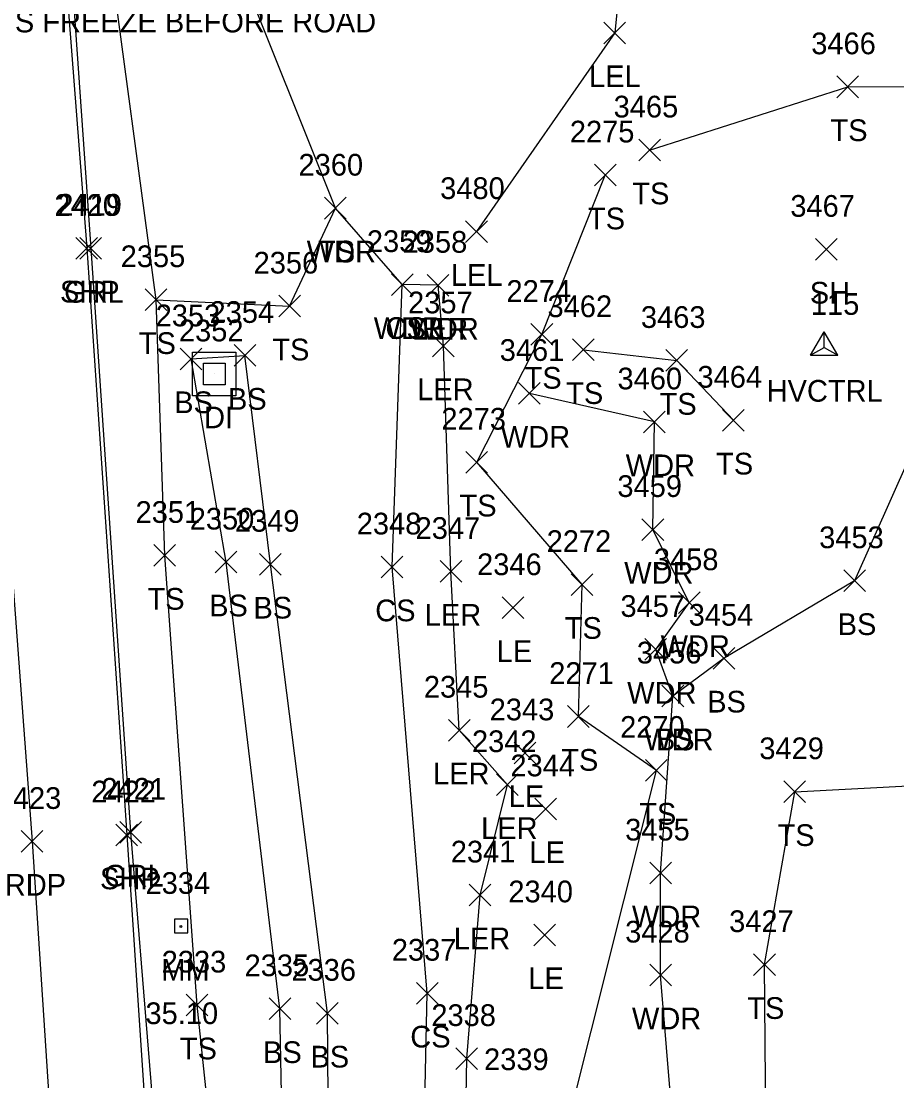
# Model space of a CAD drawing. Extents: x 1650221 to 1650634, y 244606 to 249996.
# Drawn here: x 1650339.8 to 1650420.5, y 246721.6 to 246819.2 of the extents above; entities that cross this region are included whole.
import ezdxf

# ---------------------------------------------------------------- set-up
doc = ezdxf.new("R2010")
doc.units = 0
for name, color, linetype in [('C_A', 7, 'Continuous'), ('C_I', 7, 'Continuous'), ('CPSM', 7, 'Continuous'), ('D_A', 7, 'Continuous'), ('D_I', 7, 'Continuous'), ('DS', 7, 'Continuous'), ('L_A', 7, 'Continuous'), ('L_I', 7, 'Continuous'), ('L_TIC', 7, 'Continuous'), ('LARO', 7, 'Continuous'), ('LAWA', 7, 'Continuous'), ('LELB', 7, 'Continuous'), ('P_A', 7, 'Continuous'), ('P_I', 7, 'Continuous'), ('P_TIC', 7, 'Continuous'), ('PET', 7, 'Continuous'), ('PSP', 7, 'Continuous'), ('R_A', 7, 'Continuous'), ('R_I', 7, 'Continuous'), ('R_TIC', 7, 'Continuous'), ('RGR', 7, 'Continuous'), ('S_A', 7, 'Continuous'), ('S_C', 7, 'Continuous'), ('S_I', 7, 'Continuous'), ('SRM', 7, 'Continuous')]:
    doc.layers.add(name, color=color, linetype=linetype)

msp = doc.modelspace()

# ---------------------------------------------------------------- linework, layer by layer
at = {"layer": 'CPSM'}
for p, q in [((1650412.524, 246788.462), (1650413.774, 246790.627)), ((1650415.024, 246788.462), (1650413.774, 246790.627)), ((1650413.774, 246789.183), (1650413.774, 246790.627)), ((1650412.524, 246788.462), (1650413.774, 246789.183)), ((1650413.774, 246789.183), (1650413.774, 246789.183)), ((1650413.774, 246789.183), (1650415.024, 246788.462)), ((1650412.524, 246788.462), (1650415.024, 246788.462))]:
    msp.add_line(p, q, dxfattribs=at)
at = {"layer": 'DS'}
for p, q in [((1650355.573, 246788.737), (1650359.573, 246788.737)), ((1650355.573, 246784.737), (1650355.573, 246788.737)), ((1650359.573, 246788.737), (1650359.573, 246784.737)), ((1650356.573, 246785.737), (1650356.573, 246787.737)), ((1650356.573, 246787.737), (1650358.573, 246787.737)), ((1650358.573, 246787.737), (1650358.573, 246785.737)), ((1650357.578, 246786.738), (1650357.578, 246786.738)), ((1650357.578, 246786.738), (1650357.578, 246786.738)), ((1650358.573, 246785.737), (1650356.573, 246785.737)), ((1650359.573, 246784.737), (1650355.573, 246784.737))]:
    msp.add_line(p, q, dxfattribs=at)
at = {"layer": 'L_TIC'}
for points in [[(1650393.466, 246817.159), (1650395.466, 246819.159)], [(1650395.466, 246817.159), (1650393.466, 246819.159)], [(1650414.942, 246812.191), (1650416.942, 246814.191)], [(1650416.942, 246812.191), (1650414.942, 246814.191)], [(1650396.679, 246806.368), (1650398.679, 246808.368)], [(1650398.679, 246806.368), (1650396.679, 246808.368)], [(1650392.596, 246804.064), (1650394.596, 246806.064)], [(1650394.596, 246804.064), (1650392.596, 246806.064)], [(1650367.73, 246801.011), (1650369.73, 246803.011)], [(1650369.73, 246801.011), (1650367.73, 246803.011)], [(1650367.73, 246801.011), (1650369.73, 246803.011)], [(1650369.73, 246801.011), (1650367.73, 246803.011)], [(1650380.734, 246798.853), (1650382.734, 246800.853)], [(1650382.734, 246798.853), (1650380.734, 246800.853)], [(1650412.958, 246797.218), (1650414.958, 246799.218)], [(1650414.958, 246797.218), (1650412.958, 246799.218)], [(1650373.901, 246793.969), (1650375.901, 246795.969)], [(1650375.901, 246793.969), (1650373.901, 246795.969)], [(1650373.901, 246793.969), (1650375.901, 246795.969)], [(1650375.901, 246793.969), (1650373.901, 246795.969)], [(1650377.195, 246793.908), (1650379.195, 246795.908)], [(1650379.195, 246793.908), (1650377.195, 246795.908)], [(1650377.195, 246793.908), (1650379.195, 246795.908)], [(1650379.195, 246793.908), (1650377.195, 246795.908)], [(1650351.21, 246792.578), (1650353.21, 246794.578)], [(1650353.21, 246792.578), (1650351.21, 246794.578)], [(1650351.21, 246792.578), (1650353.21, 246794.578)], [(1650353.21, 246792.578), (1650351.21, 246794.578)], [(1650363.513, 246791.988), (1650365.513, 246793.988)], [(1650365.513, 246791.988), (1650363.513, 246793.988)], [(1650386.756, 246789.379), (1650388.756, 246791.379)], [(1650388.756, 246789.379), (1650386.756, 246791.379)], [(1650377.69, 246788.322), (1650379.69, 246790.322)], [(1650379.69, 246788.322), (1650377.69, 246790.322)], [(1650390.587, 246787.973), (1650392.587, 246789.973)], [(1650392.587, 246787.973), (1650390.587, 246789.973)], [(1650354.434, 246787.128), (1650356.434, 246789.128)], [(1650356.434, 246787.128), (1650354.434, 246789.128)], [(1650359.397, 246787.442), (1650361.397, 246789.442)], [(1650361.397, 246787.442), (1650359.397, 246789.442)], [(1650359.397, 246787.442), (1650361.397, 246789.442)], [(1650361.397, 246787.442), (1650359.397, 246789.442)], [(1650399.191, 246786.98), (1650401.191, 246788.98)], [(1650401.191, 246786.98), (1650399.191, 246788.98)], [(1650385.614, 246783.942), (1650387.614, 246785.942)], [(1650387.614, 246783.942), (1650385.614, 246785.942)], [(1650397.122, 246781.319), (1650399.122, 246783.319)], [(1650399.122, 246781.319), (1650397.122, 246783.319)], [(1650404.402, 246781.475), (1650406.402, 246783.475)], [(1650406.402, 246781.475), (1650404.402, 246783.475)], [(1650380.761, 246777.609), (1650382.761, 246779.609)], [(1650382.761, 246777.609), (1650380.761, 246779.609)], [(1650396.984, 246771.405), (1650398.984, 246773.405)], [(1650398.984, 246771.405), (1650396.984, 246773.405)], [(1650352.015, 246769.02), (1650354.015, 246771.02)], [(1650354.015, 246769.02), (1650352.015, 246771.02)], [(1650357.66, 246768.405), (1650359.66, 246770.405)], [(1650359.66, 246768.405), (1650357.66, 246770.405)], [(1650361.742, 246768.205), (1650363.742, 246770.205)], [(1650363.742, 246768.205), (1650361.742, 246770.205)], [(1650372.963, 246767.954), (1650374.963, 246769.954)], [(1650374.963, 246767.954), (1650372.963, 246769.954)], [(1650378.383, 246767.543), (1650380.383, 246769.543)], [(1650380.383, 246767.543), (1650378.383, 246769.543)], [(1650390.46, 246766.336), (1650392.46, 246768.336)], [(1650392.46, 246766.336), (1650390.46, 246768.336)], [(1650415.568, 246766.686), (1650417.568, 246768.686)], [(1650417.568, 246766.686), (1650415.568, 246768.686)], [(1650384.104, 246764.204), (1650386.104, 246766.204)], [(1650386.104, 246764.204), (1650384.104, 246766.204)], [(1650400.339, 246764.659), (1650402.339, 246766.659)], [(1650402.339, 246764.659), (1650400.339, 246766.659)], [(1650397.256, 246760.358), (1650399.256, 246762.358)], [(1650399.256, 246760.358), (1650397.256, 246762.358)], [(1650403.546, 246759.548), (1650405.546, 246761.548)], [(1650405.546, 246759.548), (1650403.546, 246761.548)], [(1650398.824, 246756.067), (1650400.824, 246758.067)], [(1650400.824, 246756.067), (1650398.824, 246758.067)], [(1650398.824, 246756.067), (1650400.824, 246758.067)], [(1650400.824, 246756.067), (1650398.824, 246758.067)], [(1650390.131, 246754.182), (1650392.131, 246756.182)], [(1650392.131, 246754.182), (1650390.131, 246756.182)], [(1650379.146, 246752.919), (1650381.146, 246754.919)], [(1650381.146, 246752.919), (1650379.146, 246754.919)], [(1650385.21, 246750.83), (1650387.21, 246752.83)], [(1650387.21, 246750.83), (1650385.21, 246752.83)], [(1650397.316, 246749.216), (1650399.316, 246751.216)], [(1650399.316, 246749.216), (1650397.316, 246751.216)], [(1650383.578, 246747.9), (1650385.578, 246749.9)], [(1650385.578, 246747.9), (1650383.578, 246749.9)], [(1650410.062, 246747.25), (1650412.062, 246749.25)], [(1650412.062, 246747.25), (1650410.062, 246749.25)], [(1650387.12, 246745.67), (1650389.12, 246747.67)], [(1650389.12, 246745.67), (1650387.12, 246747.67)], [(1650397.695, 246739.756), (1650399.695, 246741.756)], [(1650399.695, 246739.756), (1650397.695, 246741.756)], [(1650381.06, 246737.733), (1650383.06, 246739.733)], [(1650383.06, 246737.733), (1650381.06, 246739.733)], [(1650387.018, 246734.061), (1650389.018, 246736.061)], [(1650389.018, 246734.061), (1650387.018, 246736.061)], [(1650407.273, 246731.321), (1650409.273, 246733.321)], [(1650409.273, 246731.321), (1650407.273, 246733.321)], [(1650397.696, 246730.357), (1650399.696, 246732.357)], [(1650399.696, 246730.357), (1650397.696, 246732.357)], [(1650376.195, 246728.688), (1650378.195, 246730.688)], [(1650378.195, 246728.688), (1650376.195, 246730.688)], [(1650354.99, 246727.594), (1650356.99, 246729.594)], [(1650356.99, 246727.594), (1650354.99, 246729.594)], [(1650362.627, 246727.256), (1650364.627, 246729.256)], [(1650364.627, 246727.256), (1650362.627, 246729.256)], [(1650366.995, 246726.841), (1650368.995, 246728.841)], [(1650368.995, 246726.841), (1650366.995, 246728.841)], [(1650379.836, 246722.666), (1650381.836, 246724.666)], [(1650381.836, 246722.666), (1650379.836, 246724.666)]]:
    msp.add_lwpolyline(points, dxfattribs=at)
at = {"layer": 'LARO'}
for points in [[(1650457.471, 246862.18), (1650434.864, 246856.289), (1650411.097, 246851.446), (1650396.793, 246841.425), (1650394.466, 246818.159), (1650381.734, 246799.853)], [(1650385.03, 246598.745), (1650385.051, 246648.918), (1650383.043, 246669.852), (1650384.507, 246678.757), (1650380.148, 246683.581), (1650380.836, 246723.666), (1650382.06, 246738.733), (1650384.578, 246748.9), (1650380.146, 246753.919), (1650379.383, 246768.543), (1650378.69, 246789.322), (1650378.195, 246794.908)]]:
    msp.add_lwpolyline(points, dxfattribs=at)
at = {"layer": 'LAWA'}
for points in [[(1650378.195, 246794.908), (1650374.901, 246794.969), (1650368.73, 246802.011), (1650359.684, 246824.662), (1650349.32, 246871.738), (1650348.019, 246917.211), (1650345.502, 246965.532), (1650341.283, 247016.153), (1650338.12, 247059.964), (1650335.104, 247106.885), (1650329.408, 247153.665), (1650323.249, 247198.71), (1650318.643, 247242.09)], [(1650408.993, 246611.27), (1650406.472, 246635.271), (1650404.881, 246672.462), (1650402.031, 246691.004), (1650398.696, 246731.357), (1650398.695, 246740.756), (1650399.824, 246757.067), (1650398.256, 246761.358), (1650401.339, 246765.659), (1650397.984, 246772.405), (1650398.122, 246782.319), (1650386.614, 246784.942)]]:
    msp.add_lwpolyline(points, dxfattribs=at)
at = {"layer": 'LELB'}
for points in [[(1650393.271, 246215.062), (1650388.589, 246258.034), (1650385.303, 246297.22), (1650382.892, 246338.269), (1650379.783, 246382.543), (1650376.697, 246415.11), (1650373.391, 246460.521), (1650370.351, 246509.107), (1650367.729, 246551.788), (1650362.786, 246601.351), (1650360.906, 246643.926), (1650360.73, 246683.447), (1650355.99, 246728.594), (1650353.015, 246770.02), (1650352.21, 246793.578), (1650347.695, 246827.184)], [(1650397.679, 246807.368), (1650415.942, 246813.191), (1650432.774, 246813.271), (1650445.833, 246821.166), (1650460.046, 246825.274)], [(1650402.921, 246599.271), (1650397.783, 246634.795), (1650394.567, 246669.219), (1650391.512, 246693.687), (1650389.291, 246714.189), (1650398.316, 246750.216), (1650391.131, 246755.182), (1650391.46, 246767.336), (1650381.761, 246778.609), (1650387.756, 246790.379), (1650393.596, 246805.064)], [(1650352.21, 246793.578), (1650364.513, 246792.988), (1650368.73, 246802.011)], [(1650441.902, 246800.841), (1650424.95, 246786.506), (1650416.568, 246767.686), (1650404.546, 246760.548), (1650399.824, 246757.067)], [(1650415.884, 246671.758), (1650408.611, 246692.745), (1650408.273, 246732.321), (1650411.062, 246748.25), (1650427.903, 246749.136), (1650447.805, 246762.502), (1650450.817, 246774.888), (1650455.51, 246787.223), (1650459.197, 246795.668)], [(1650406.656, 246218.25), (1650409.738, 246258.013), (1650404.964, 246296.74), (1650400.855, 246340.502), (1650395.586, 246379.715), (1650393.167, 246415.096), (1650394.545, 246457.778), (1650389.364, 246506.838), (1650386.116, 246550.614), (1650380.924, 246598.971), (1650378.983, 246645.95), (1650376.234, 246684.957), (1650377.195, 246729.688), (1650373.963, 246768.954), (1650374.901, 246794.969)], [(1650391.587, 246788.973), (1650400.191, 246787.98), (1650405.402, 246782.475)], [(1650398.424, 246215.354), (1650393.502, 246258.252), (1650390.33, 246297.072), (1650387.572, 246339.17), (1650383.093, 246382.589), (1650381.544, 246415.749), (1650379.325, 246460.798), (1650374.717, 246508.954), (1650372.604, 246551.632), (1650368.85, 246601.305), (1650366.306, 246644.434), (1650364.471, 246684.577), (1650363.627, 246728.256), (1650358.66, 246769.405), (1650355.434, 246788.128), (1650360.397, 246788.442)], [(1650402.25, 246216.694), (1650398.468, 246258.758), (1650395.79, 246297.148), (1650391.97, 246340.099), (1650387.542, 246382.066), (1650385.712, 246415.977), (1650383.049, 246460.21), (1650379.089, 246508.869), (1650375.792, 246552.139), (1650373.138, 246601), (1650370.951, 246644.961), (1650368.354, 246684.963), (1650367.995, 246727.841), (1650362.742, 246769.205), (1650360.397, 246788.442)]]:
    msp.add_lwpolyline(points, dxfattribs=at)
at = {"layer": 'P_TIC'}
for points in [[(1650344.817, 246797.321), (1650346.817, 246799.321)], [(1650346.817, 246797.321), (1650344.817, 246799.321)], [(1650339.787, 246742.668), (1650341.787, 246744.668)], [(1650341.787, 246742.668), (1650339.787, 246744.668)], [(1650348.506, 246743.265), (1650350.506, 246745.265)], [(1650350.506, 246743.265), (1650348.506, 246745.265)]]:
    msp.add_lwpolyline(points, dxfattribs=at)
at = {"layer": 'PET'}
msp.add_lwpolyline([(1650303.592, 247255.037), (1650306.806, 247216.139), (1650310.511, 247167.041), (1650313.873, 247117.506), (1650317.794, 247067.135), (1650321.462, 247013.252), (1650325.737, 246955.862), (1650329.2, 246907.195), (1650332.986, 246853.312), (1650336.639, 246798.797), (1650340.787, 246743.668), (1650343.552, 246701.317), (1650346.095, 246667.406)], dxfattribs=at)
at = {"layer": 'PSP'}
msp.add_lwpolyline([(1650307.744, 247242.22), (1650310.229, 247216.37), (1650315.188, 247167.556), (1650319.936, 247117.425), (1650324.846, 247068.004), (1650329.683, 247013.471), (1650333.891, 246957.271), (1650337.469, 246907.247), (1650341.57, 246853.304), (1650345.817, 246798.321), (1650349.506, 246744.265), (1650352.382, 246701.379), (1650355.129, 246668.21)], dxfattribs=at)
at = {"layer": 'R_TIC'}
for points in [[(1650345.19, 246797.302), (1650347.19, 246799.302)], [(1650347.19, 246797.302), (1650345.19, 246799.302)], [(1650348.87, 246743.517), (1650350.87, 246745.517)], [(1650350.87, 246743.517), (1650348.87, 246745.517)]]:
    msp.add_lwpolyline(points, dxfattribs=at)
at = {"layer": 'RGR'}
msp.add_lwpolyline([(1650308.184, 247241.072), (1650310.553, 247216.531), (1650315.545, 247167.769), (1650320.435, 247117.508), (1650325.421, 247068.178), (1650330.464, 247013.433), (1650334.737, 246957.482), (1650338.488, 246907.233), (1650342.309, 246853.815), (1650346.19, 246798.302), (1650349.87, 246744.517), (1650353.369, 246701.532), (1650355.68, 246682.238), (1650357.827, 246668.942)], dxfattribs=at)
at = {"layer": 'SRM'}
for p, q in [((1650355.153, 246736.498), (1650353.903, 246736.498)), ((1650353.903, 246736.498), (1650353.903, 246735.248)), ((1650355.153, 246736.498), (1650353.903, 246736.498)), ((1650353.903, 246736.498), (1650353.903, 246735.248)), ((1650355.153, 246735.248), (1650355.153, 246736.498)), ((1650355.153, 246735.248), (1650355.153, 246736.498)), ((1650353.903, 246735.248), (1650355.153, 246735.248)), ((1650353.903, 246735.248), (1650355.153, 246735.248))]:
    msp.add_line(p, q, dxfattribs=at)
msp.add_circle((1650354.504, 246735.836), 0.0833, dxfattribs=at)

# ---------------------------------------------------------------- texts
at = {"layer": 'C_A'}
msp.add_text('HVCTRL', height=2, dxfattribs=at).set_placement((1650408.467, 246784.183))
at = {"layer": 'C_I'}
msp.add_text('115', height=2, dxfattribs=at).set_placement((1650412.546, 246792.183))
at = {"layer": 'D_A'}
msp.add_text('DI', height=2, dxfattribs=at).set_placement((1650356.634, 246781.738))
at = {"layer": 'D_I'}
msp.add_text('2352', height=2, dxfattribs=at).set_placement((1650354.319, 246789.738))
at = {"layer": 'L_A'}
for s, p in [('LEL', (1650392.104, 246813.159)), ('TS', (1650414.351, 246808.191)), ('TS', (1650396.089, 246802.368)), ('TS', (1650392.005, 246800.064)), ('WDR', (1650366.092, 246797.011)), ('TS', (1650367.139, 246797.011)), ('LEL', (1650379.371, 246794.853)), ('SH', (1650412.446, 246793.218)), ('WDR', (1650372.264, 246789.969)), ('CS', (1650373.342, 246789.969)), ('WDR', (1650375.558, 246789.908)), ('LER', (1650375.778, 246789.908)), ('TS', (1650350.619, 246788.578)), ('TS', (1650350.619, 246788.578)), ('TS', (1650362.923, 246787.988)), ('TS', (1650386.166, 246785.379)), ('LER', (1650376.272, 246784.322)), ('TS', (1650389.997, 246783.973)), ('BS', (1650353.875, 246783.128)), ('BS', (1650358.838, 246783.442)), ('BS', (1650358.838, 246783.442)), ('TS', (1650398.601, 246782.98)), ('WDR', (1650383.977, 246779.942)), ('WDR', (1650395.484, 246777.319)), ('TS', (1650403.812, 246777.475)), ('TS', (1650380.17, 246773.609)), ('WDR', (1650395.346, 246767.405)), ('TS', (1650351.424, 246765.02)), ('BS', (1650357.101, 246764.405)), ('BS', (1650361.183, 246764.205)), ('CS', (1650372.404, 246763.954)), ('LER', (1650376.966, 246763.543)), ('TS', (1650389.869, 246762.336)), ('BS', (1650415.009, 246762.686)), ('WDR', (1650398.701, 246760.659)), ('LE', (1650383.592, 246760.204)), ('WDR', (1650395.619, 246756.358)), ('BS', (1650402.987, 246755.548)), ('WDR', (1650397.186, 246752.067)), ('BS', (1650398.265, 246752.067)), ('TS', (1650389.54, 246750.182)), ('LER', (1650377.729, 246748.919)), ('LE', (1650384.698, 246746.83)), ('TS', (1650396.726, 246745.216)), ('LER', (1650382.16, 246743.9)), ('TS', (1650409.472, 246743.25)), ('LE', (1650386.609, 246741.67)), ('WDR', (1650396.057, 246735.756)), ('LER', (1650379.642, 246733.733)), ('LE', (1650386.506, 246730.061)), ('TS', (1650406.683, 246727.321)), ('WDR', (1650396.058, 246726.357)), ('CS', (1650375.635, 246724.688)), ('TS', (1650354.4, 246723.594)), ('BS', (1650362.068, 246723.256)), ('BS', (1650366.436, 246722.841))]:
    msp.add_text(s, height=2, dxfattribs=at).set_placement(p)
at = {"layer": 'L_I'}
for s, p in [('3466', (1650412.58, 246816.191)), ('3465', (1650394.372, 246810.368)), ('2275', (1650390.336, 246808.064)), ('2360', (1650365.336, 246805.011)), ('2360', (1650365.336, 246805.011)), ('3480', (1650378.387, 246802.853)), ('3467', (1650410.651, 246801.218)), ('2359', (1650371.634, 246797.969)), ('2359', (1650371.634, 246797.969)), ('2358', (1650374.935, 246797.908)), ('2358', (1650374.935, 246797.908)), ('2355', (1650348.95, 246796.578)), ('2355', (1650348.95, 246796.578)), ('2356', (1650361.198, 246795.988)), ('2274', (1650384.496, 246793.379)), ('2354', (1650357.137, 246791.442)), ('2354', (1650357.137, 246791.442)), ('2357', (1650375.43, 246792.322)), ('3462', (1650388.28, 246791.973)), ('2353', (1650352.174, 246791.128)), ('3463', (1650396.884, 246790.98)), ('3461', (1650383.874, 246787.942)), ('3460', (1650394.728, 246785.319)), ('3464', (1650402.095, 246785.475)), ('2273', (1650378.501, 246781.609)), ('3459', (1650394.716, 246775.405)), ('2351', (1650350.322, 246773.02)), ('2350', (1650355.314, 246772.405)), ('2349', (1650359.475, 246772.205)), ('2348', (1650370.703, 246771.954)), ('2347', (1650376.123, 246771.543)), ('2272', (1650388.2, 246770.336)), ('3453', (1650413.308, 246770.686)), ('2346', (1650381.789, 246768.204)), ('3458', (1650398.079, 246768.659)), ('3457', (1650394.997, 246764.358)), ('3454', (1650401.286, 246763.548)), ('3456', (1650396.509, 246760.067)), ('3456', (1650396.509, 246760.067)), ('2271', (1650388.438, 246758.182)), ('2345', (1650376.886, 246756.919)), ('2343', (1650382.95, 246754.83)), ('2270', (1650394.97, 246753.216)), ('2342', (1650381.318, 246751.9)), ('3429', (1650407.795, 246751.25)), ('2344', (1650384.861, 246749.67)), ('3455', (1650395.435, 246743.756)), ('2341', (1650379.367, 246741.733)), ('2340', (1650384.672, 246738.061)), ('3427', (1650405.013, 246735.321)), ('3428', (1650395.436, 246734.357)), ('2337', (1650373.935, 246732.688)), ('2333', (1650352.73, 246731.594)), ('2335', (1650360.367, 246731.256)), ('2336', (1650364.68, 246730.841)), ('2338', (1650377.576, 246726.666)), ('2339', (1650382.432, 246722.599))]:
    msp.add_text(s, height=2, dxfattribs=at).set_placement(p)
at = {"layer": 'P_A'}
for s, p in [('SHP', (1650343.353, 246793.321)), ('SHP', (1650347.042, 246739.265)), ('RDP', (1650338.275, 246738.668))]:
    msp.add_text(s, height=2, dxfattribs=at).set_placement(p)
at = {"layer": 'P_I'}
for s, p in [('2419', (1650343.116, 246801.321)), ('2423', (1650337.527, 246746.668)), ('2422', (1650346.246, 246747.265))]:
    msp.add_text(s, height=2, dxfattribs=at).set_placement(p)
at = {"layer": 'R_A'}
for p in [(1650343.733, 246793.302), (1650347.413, 246739.517)]:
    msp.add_text('GRL', height=2, dxfattribs=at).set_placement(p)
at = {"layer": 'R_I'}
for s, p in [('2420', (1650342.843, 246801.302)), ('2421', (1650347.177, 246747.517))]:
    msp.add_text(s, height=2, dxfattribs=at).set_placement(p)
at = {"layer": 'S_A'}
msp.add_text('MM', height=2, dxfattribs=at).set_placement((1650352.692, 246730.841))
at = {"layer": 'S_C'}
for s, p in [('BRIDGES FREEZE BEFORE ROAD', (1650328.948, 246818.205)), ('35.10', (1650351.235, 246726.841))]:
    msp.add_text(s, height=2, dxfattribs=at).set_placement(p)
at = {"layer": 'S_I'}
msp.add_text('2334', height=2, dxfattribs=at).set_placement((1650351.243, 246738.841))

doc.saveas('drawing.dxf')
